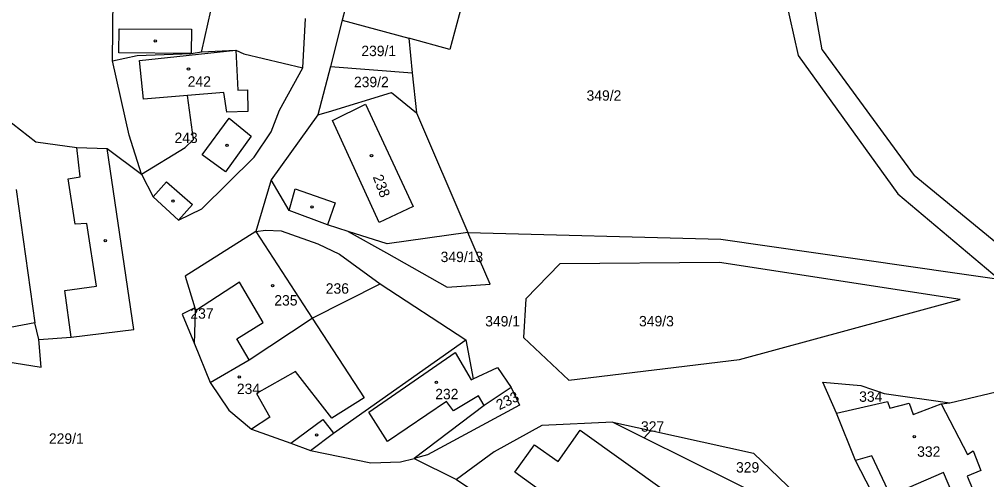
# Model space of a CAD drawing. Extents: x -563148 to -561712, y -1182311 to -1179502.
# Drawn here: x -562585.8 to -562446.2, y -1180315.1 to -1180248.7 of the extents above; entities that cross this region are included whole.
import ezdxf

# ---------------------------------------------------------------- set-up
doc = ezdxf.new("R2010")
doc.units = 0
for name, color, linetype in [('Vrstva 55', 7, 'Continuous'), ('Vrstva 56', 7, 'Continuous'), ('Vrstva 57', 7, 'Continuous')]:
    doc.layers.add(name, color=color, linetype=linetype)

msp = doc.modelspace()

# ---------------------------------------------------------------- linework, layer by layer
at = {"layer": 'Vrstva 55'}
for p, q in [((-562469.96, -1180253.12), (-562478.42, -1180205.34)), ((-562482.99, -1180211.29), (-562473.41, -1180253.94)), ((-562516.64, -1180226.92), (-562523.68, -1180253.05)), ((-562559.44, -1180253.27), (-562556.77, -1180241.34)), ((-562537.34, -1180241.54), (-562539.18, -1180248.86)), ((-562572.34, -1180254.7), (-562572.21, -1180243.66)), ((-562544.86, -1180255.73), (-562544.47, -1180248.58)), ((-562539.18, -1180248.86), (-562540.88, -1180255.5)), ((-562539.18, -1180248.86), (-562529.59, -1180251.45)), ((-562523.68, -1180253.05), (-562529.59, -1180251.45)), ((-562529.59, -1180251.45), (-562529.08, -1180256.42)), ((-562600.58, -1180252.99), (-562583.38, -1180266.4)), ((-562572.34, -1180254.7), (-562568.77, -1180253.94)), ((-562568.77, -1180253.94), (-562560.98, -1180253.63)), ((-562568.43, -1180254.63), (-562554.54, -1180253.15)), ((-562560.98, -1180253.63), (-562559.47, -1180253.42)), ((-562559.47, -1180253.42), (-562554.54, -1180253.15)), ((-562559.47, -1180253.42), (-562559.44, -1180253.27)), ((-562554.54, -1180253.15), (-562553.37, -1180253.71)), ((-562553.37, -1180253.71), (-562544.86, -1180255.73)), ((-562473.41, -1180253.94), (-562459.04, -1180273.89)), ((-562469.96, -1180253.12), (-562456.67, -1180271.23)), ((-562569.94, -1180265.44), (-562572.34, -1180254.7)), ((-562567.86, -1180260.23), (-562568.43, -1180254.63)), ((-562540.88, -1180255.5), (-562542.68, -1180262.5)), ((-562540.88, -1180255.5), (-562529.08, -1180256.42)), ((-562548.22, -1180261.82), (-562544.86, -1180255.73)), ((-562529.08, -1180256.42), (-562528.49, -1180262.21)), ((-562541.18, -1180262.05), (-562532.1, -1180259.27)), ((-562532.1, -1180259.27), (-562528.49, -1180262.21)), ((-562561.51, -1180259.71), (-562567.86, -1180260.23)), ((-562560.63, -1180266.03), (-562561.51, -1180259.71)), ((-562549.44, -1180264.95), (-562548.22, -1180261.82)), ((-562542.68, -1180262.5), (-562541.18, -1180262.05)), ((-562528.49, -1180262.21), (-562521.08, -1180279.47)), ((-562542.68, -1180262.5), (-562549.42, -1180271.85)), ((-562551.91, -1180268.58), (-562549.44, -1180264.95)), ((-562583.38, -1180266.4), (-562577.46, -1180267.18)), ((-562568.16, -1180271.03), (-562569.94, -1180265.44)), ((-562561.86, -1180267.2), (-562560.63, -1180266.03)), ((-562577.46, -1180267.18), (-562573.11, -1180267.32)), ((-562573.11, -1180267.32), (-562568.16, -1180271.03)), ((-562569.25, -1180293.42), (-562573.11, -1180267.32)), ((-562568.16, -1180271.03), (-562561.86, -1180267.2)), ((-562559.45, -1180276.04), (-562551.91, -1180268.58)), ((-562568.16, -1180271.03), (-562566.48, -1180274.31)), ((-562549.42, -1180271.85), (-562551.66, -1180279.33)), ((-562546.82, -1180276.29), (-562549.42, -1180271.85)), ((-562438.43, -1180286.22), (-562456.67, -1180271.23)), ((-562566.48, -1180274.31), (-562562.78, -1180277.66)), ((-562459.04, -1180273.89), (-562444.43, -1180286.2)), ((-562562.78, -1180277.66), (-562559.45, -1180276.04)), ((-562541.32, -1180278.35), (-562546.82, -1180276.29)), ((-562551.66, -1180279.33), (-562550.27, -1180279.11)), ((-562550.27, -1180279.11), (-562547.97, -1180279.23)), ((-562538.34, -1180279.29), (-562541.32, -1180278.35)), ((-562551.66, -1180279.33), (-562561.83, -1180285.73)), ((-562551.66, -1180279.33), (-562543.52, -1180291.8)), ((-562547.97, -1180279.23), (-562542.72, -1180281.11)), ((-562538.34, -1180279.29), (-562532.79, -1180282.4)), ((-562532.68, -1180281.08), (-562538.34, -1180279.29)), ((-562521.08, -1180279.47), (-562532.68, -1180281.08)), ((-562521.08, -1180279.47), (-562484.57, -1180280.44)), ((-562517.84, -1180286.9), (-562521.08, -1180279.47)), ((-562484.57, -1180280.44), (-562450.47, -1180285.34)), ((-562542.72, -1180281.11), (-562539.56, -1180282.58)), ((-562539.56, -1180282.58), (-562533.73, -1180286.88)), ((-562532.79, -1180282.4), (-562524.05, -1180287.33)), ((-562507.8, -1180283.99), (-562512.72, -1180289.04)), ((-562484.75, -1180283.78), (-562507.8, -1180283.99)), ((-562450.05, -1180289.13), (-562484.75, -1180283.78)), ((-562561.83, -1180285.73), (-562560.46, -1180290.33)), ((-562450.47, -1180285.34), (-562444.43, -1180286.2)), ((-562543.52, -1180291.8), (-562533.73, -1180286.88)), ((-562533.73, -1180286.88), (-562521.37, -1180294.95)), ((-562524.05, -1180287.33), (-562517.84, -1180286.9)), ((-562560.46, -1180290.33), (-562562.25, -1180291.22)), ((-562560.36, -1180290.77), (-562560.46, -1180290.33)), ((-562512.72, -1180289.04), (-562513.04, -1180294.59)), ((-562481.88, -1180297.77), (-562450.05, -1180289.13)), ((-562562.25, -1180291.22), (-562560.5, -1180295.51)), ((-562560.5, -1180295.51), (-562560.36, -1180290.77)), ((-562583.53, -1180292.49), (-562593.74, -1180294.4)), ((-562582.94, -1180294.87), (-562583.53, -1180292.49)), ((-562552.6, -1180297.81), (-562543.52, -1180291.8)), ((-562582.94, -1180294.87), (-562578.27, -1180294.56)), ((-562578.27, -1180294.56), (-562569.25, -1180293.42)), ((-562582.6, -1180298.87), (-562582.94, -1180294.87)), ((-562560.5, -1180295.51), (-562558.23, -1180301.07)), ((-562540.43, -1180308.38), (-562521.37, -1180294.95)), ((-562521.37, -1180294.95), (-562520.3, -1180300.58)), ((-562513.04, -1180294.59), (-562506.5, -1180300.73)), ((-562591.85, -1180297.37), (-562582.6, -1180298.87)), ((-562558.23, -1180301.07), (-562552.6, -1180297.81)), ((-562506.5, -1180300.73), (-562481.88, -1180297.77)), ((-562520.3, -1180300.58), (-562516.77, -1180298.9)), ((-562516.77, -1180298.9), (-562514.8, -1180301.8)), ((-562558.23, -1180301.07), (-562555.53, -1180305.06)), ((-562469.86, -1180301.06), (-562464.36, -1180301.51)), ((-562467.9, -1180305.5), (-562469.86, -1180301.06)), ((-562464.36, -1180301.51), (-562461.02, -1180302.68)), ((-562451.53, -1180304.01), (-562438.23, -1180300.88)), ((-562514.8, -1180301.8), (-562518.7, -1180304.39)), ((-562514.8, -1180301.8), (-562513.62, -1180304.35)), ((-562461.02, -1180302.68), (-562451.53, -1180304.01)), ((-562467.9, -1180305.5), (-562460.53, -1180303.84)), ((-562460.53, -1180303.84), (-562460.2, -1180304.79)), ((-562460.2, -1180304.79), (-562457.4, -1180304.05)), ((-562457.4, -1180304.05), (-562456.85, -1180305.71)), ((-562456.85, -1180305.71), (-562452.78, -1180304.15)), ((-562452.78, -1180304.15), (-562451.53, -1180304.01)), ((-562452.78, -1180304.15), (-562449, -1180311.49)), ((-562555.53, -1180305.06), (-562552.26, -1180307.83)), ((-562518.7, -1180304.39), (-562528.83, -1180312.03)), ((-562513.62, -1180304.35), (-562526.9, -1180311.52)), ((-562465.16, -1180312.35), (-562467.9, -1180305.5)), ((-562500.16, -1180306.82), (-562510.39, -1180307.29)), ((-562500.16, -1180306.82), (-562494.68, -1180308.02)), ((-562500.16, -1180306.82), (-562495.65, -1180309.05)), ((-562552.26, -1180307.83), (-562546.62, -1180309.85)), ((-562543.78, -1180310.89), (-562540.43, -1180308.38)), ((-562510.39, -1180307.29), (-562517.29, -1180311.08)), ((-562494.68, -1180308.02), (-562495.65, -1180309.05)), ((-562494.68, -1180308.02), (-562479.85, -1180311.29)), ((-562546.62, -1180309.85), (-562543.78, -1180310.89)), ((-562495.65, -1180309.05), (-562467.72, -1180322.87)), ((-562543.78, -1180310.89), (-562535.07, -1180312.66)), ((-562517.29, -1180311.08), (-562522.69, -1180315.08)), ((-562479.85, -1180311.29), (-562467.72, -1180322.87)), ((-562449, -1180311.49), (-562448.18, -1180310.94)), ((-562448.18, -1180310.94), (-562447.07, -1180313.79)), ((-562535.07, -1180312.66), (-562530.8, -1180312.54)), ((-562530.8, -1180312.54), (-562528.83, -1180312.03)), ((-562526.9, -1180311.52), (-562528.83, -1180312.03)), ((-562528.83, -1180312.03), (-562522.69, -1180315.08)), ((-562461.33, -1180319.64), (-562465.16, -1180312.35)), ((-562447.07, -1180313.79), (-562449.02, -1180314.6)), ((-562522.69, -1180315.08), (-562506.45, -1180325.98)), ((-562449.02, -1180314.6), (-562447.52, -1180318.24))]:
    msp.add_line(p, q, dxfattribs=at)
at = {"layer": 'Vrstva 56'}
for p, q in [((-562571.39, -1180253.56), (-562571.35, -1180250.07)), ((-562571.35, -1180250.07), (-562560.95, -1180250.13)), ((-562560.95, -1180250.13), (-562560.98, -1180253.63)), ((-562560.98, -1180253.63), (-562571.39, -1180253.56)), ((-562554.54, -1180253.15), (-562554.24, -1180258.91)), ((-562556.26, -1180259.27), (-562561.51, -1180259.71)), ((-562555.83, -1180262.12), (-562556.26, -1180259.27)), ((-562554.24, -1180258.91), (-562552.84, -1180258.89)), ((-562552.84, -1180258.89), (-562552.8, -1180262.01)), ((-562540.6, -1180263.31), (-562535.85, -1180260.95)), ((-562535.85, -1180260.95), (-562528.96, -1180275.69)), ((-562552.8, -1180262.01), (-562555.83, -1180262.12)), ((-562559.4, -1180268.28), (-562555.47, -1180262.98)), ((-562555.47, -1180262.98), (-562552.32, -1180265.55)), ((-562533.85, -1180278.02), (-562540.6, -1180263.31)), ((-562552.32, -1180265.55), (-562556.04, -1180270.71)), ((-562577, -1180271.42), (-562577.46, -1180267.18)), ((-562556.04, -1180270.71), (-562559.4, -1180268.28)), ((-562578.74, -1180271.7), (-562577, -1180271.42)), ((-562577.69, -1180278.27), (-562578.74, -1180271.7)), ((-562566.48, -1180274.31), (-562564.51, -1180272.15)), ((-562564.51, -1180272.15), (-562560.77, -1180275.44)), ((-562586.23, -1180273.26), (-562583.53, -1180292.49)), ((-562546.82, -1180276.29), (-562545.98, -1180273.18)), ((-562545.98, -1180273.18), (-562540.21, -1180275.2)), ((-562560.77, -1180275.44), (-562562.78, -1180277.66)), ((-562540.21, -1180275.2), (-562541.32, -1180278.35)), ((-562528.96, -1180275.69), (-562533.85, -1180278.02)), ((-562576.04, -1180278.17), (-562577.69, -1180278.27)), ((-562574.64, -1180287.19), (-562576.04, -1180278.17)), ((-562579.21, -1180287.83), (-562574.64, -1180287.19)), ((-562553.98, -1180286.64), (-562560.36, -1180290.77)), ((-562550.57, -1180292.43), (-562553.98, -1180286.64)), ((-562578.27, -1180294.56), (-562579.21, -1180287.83)), ((-562554.38, -1180294.79), (-562550.57, -1180292.43)), ((-562543.52, -1180291.8), (-562536.02, -1180303.3)), ((-562552.6, -1180297.81), (-562554.38, -1180294.79)), ((-562535.34, -1180305.37), (-562522.91, -1180296.76)), ((-562522.91, -1180296.76), (-562520.57, -1180300.71)), ((-562545.94, -1180299.49), (-562551.57, -1180302.69)), ((-562540.7, -1180306.22), (-562545.94, -1180299.49)), ((-562520.57, -1180300.71), (-562520.3, -1180300.58)), ((-562551.57, -1180302.69), (-562549.65, -1180306.08)), ((-562536.02, -1180303.3), (-562540.7, -1180306.22)), ((-562524.15, -1180303.83), (-562532.66, -1180309.58)), ((-562523.14, -1180305.18), (-562524.15, -1180303.83)), ((-562519.53, -1180303.02), (-562523.14, -1180305.18)), ((-562518.7, -1180304.39), (-562519.53, -1180303.02)), ((-562532.66, -1180309.58), (-562535.34, -1180305.37)), ((-562549.65, -1180306.08), (-562552.26, -1180307.83)), ((-562546.62, -1180309.85), (-562541.97, -1180306.4)), ((-562541.97, -1180306.4), (-562540.43, -1180308.38)), ((-562508.03, -1180312.47), (-562504.85, -1180307.96)), ((-562504.85, -1180307.96), (-562492.35, -1180316.9)), ((-562514.27, -1180314.03), (-562511.44, -1180310.06)), ((-562511.44, -1180310.06), (-562508.03, -1180312.47)), ((-562462.81, -1180311.66), (-562465.16, -1180312.35)), ((-562460.12, -1180317.39), (-562462.81, -1180311.66)), ((-562498.37, -1180325.47), (-562514.27, -1180314.03)), ((-562452.47, -1180314.07), (-562460.12, -1180317.39)), ((-562451.24, -1180316.91), (-562452.47, -1180314.07))]:
    msp.add_line(p, q, dxfattribs=at)
at = {"layer": 'Vrstva 57'}
for centre in [(-562566.16, -1180251.84), (-562561.36, -1180255.88), (-562555.79, -1180266.89), (-562534.96, -1180268.36), (-562563.6, -1180274.93), (-562543.54, -1180275.77), (-562573.36, -1180280.62), (-562549.23, -1180287.11), (-562554.03, -1180300.28), (-562525.61, -1180301.07), (-562542.88, -1180308.65), (-562456.67, -1180308.89)]:
    msp.add_circle(centre, 0.175, dxfattribs=at)

# ---------------------------------------------------------------- texts
for s, p in [('239/1', (-562536.43, -1180254.02)), ('242', (-562561.47, -1180258.43)), ('239/2', (-562537.49, -1180258.5)), ('349/2', (-562503.94, -1180260.45)), ('243', (-562563.38, -1180266.55)), ('349/13', (-562524.99, -1180283.72)), ('236', (-562541.56, -1180288.28)), ('235', (-562548.98, -1180289.99)), ('237', (-562561.09, -1180291.88)), ('349/1', (-562518.56, -1180293)), ('349/3', (-562496.37, -1180292.99)), ('234', (-562554.38, -1180302.75)), ('232', (-562525.77, -1180303.5)), ('334', (-562464.62, -1180303.87)), ('327', (-562496.09, -1180308.18)), ('229/1', (-562581.49, -1180309.92)), ('332', (-562456.25, -1180311.8)), ('329', (-562482.38, -1180314.07))]:
    msp.add_text(s, height=1.5, dxfattribs=at).set_placement(p)
for s, rotation, p in [('238', 290.4418, (-562534.8, -1180271.43)), ('233', 25.9034, (-562516.52, -1180305.1))]:
    msp.add_text(s, height=1.5, rotation=rotation, dxfattribs=at).set_placement(p)

doc.saveas('drawing.dxf')
